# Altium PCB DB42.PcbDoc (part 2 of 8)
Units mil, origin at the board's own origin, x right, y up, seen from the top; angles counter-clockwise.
Board outline 3236.22 x 4456.69 mil, 8 copper layers (Top Layer, MidLayer1, MidLayer2, GND-Layer5, MidLayer3, VCC, MidLayer4, Bottom Layer), stack 62.194 mil thick; 214 components, 470 nets, 1802 pads, 1663 vias.
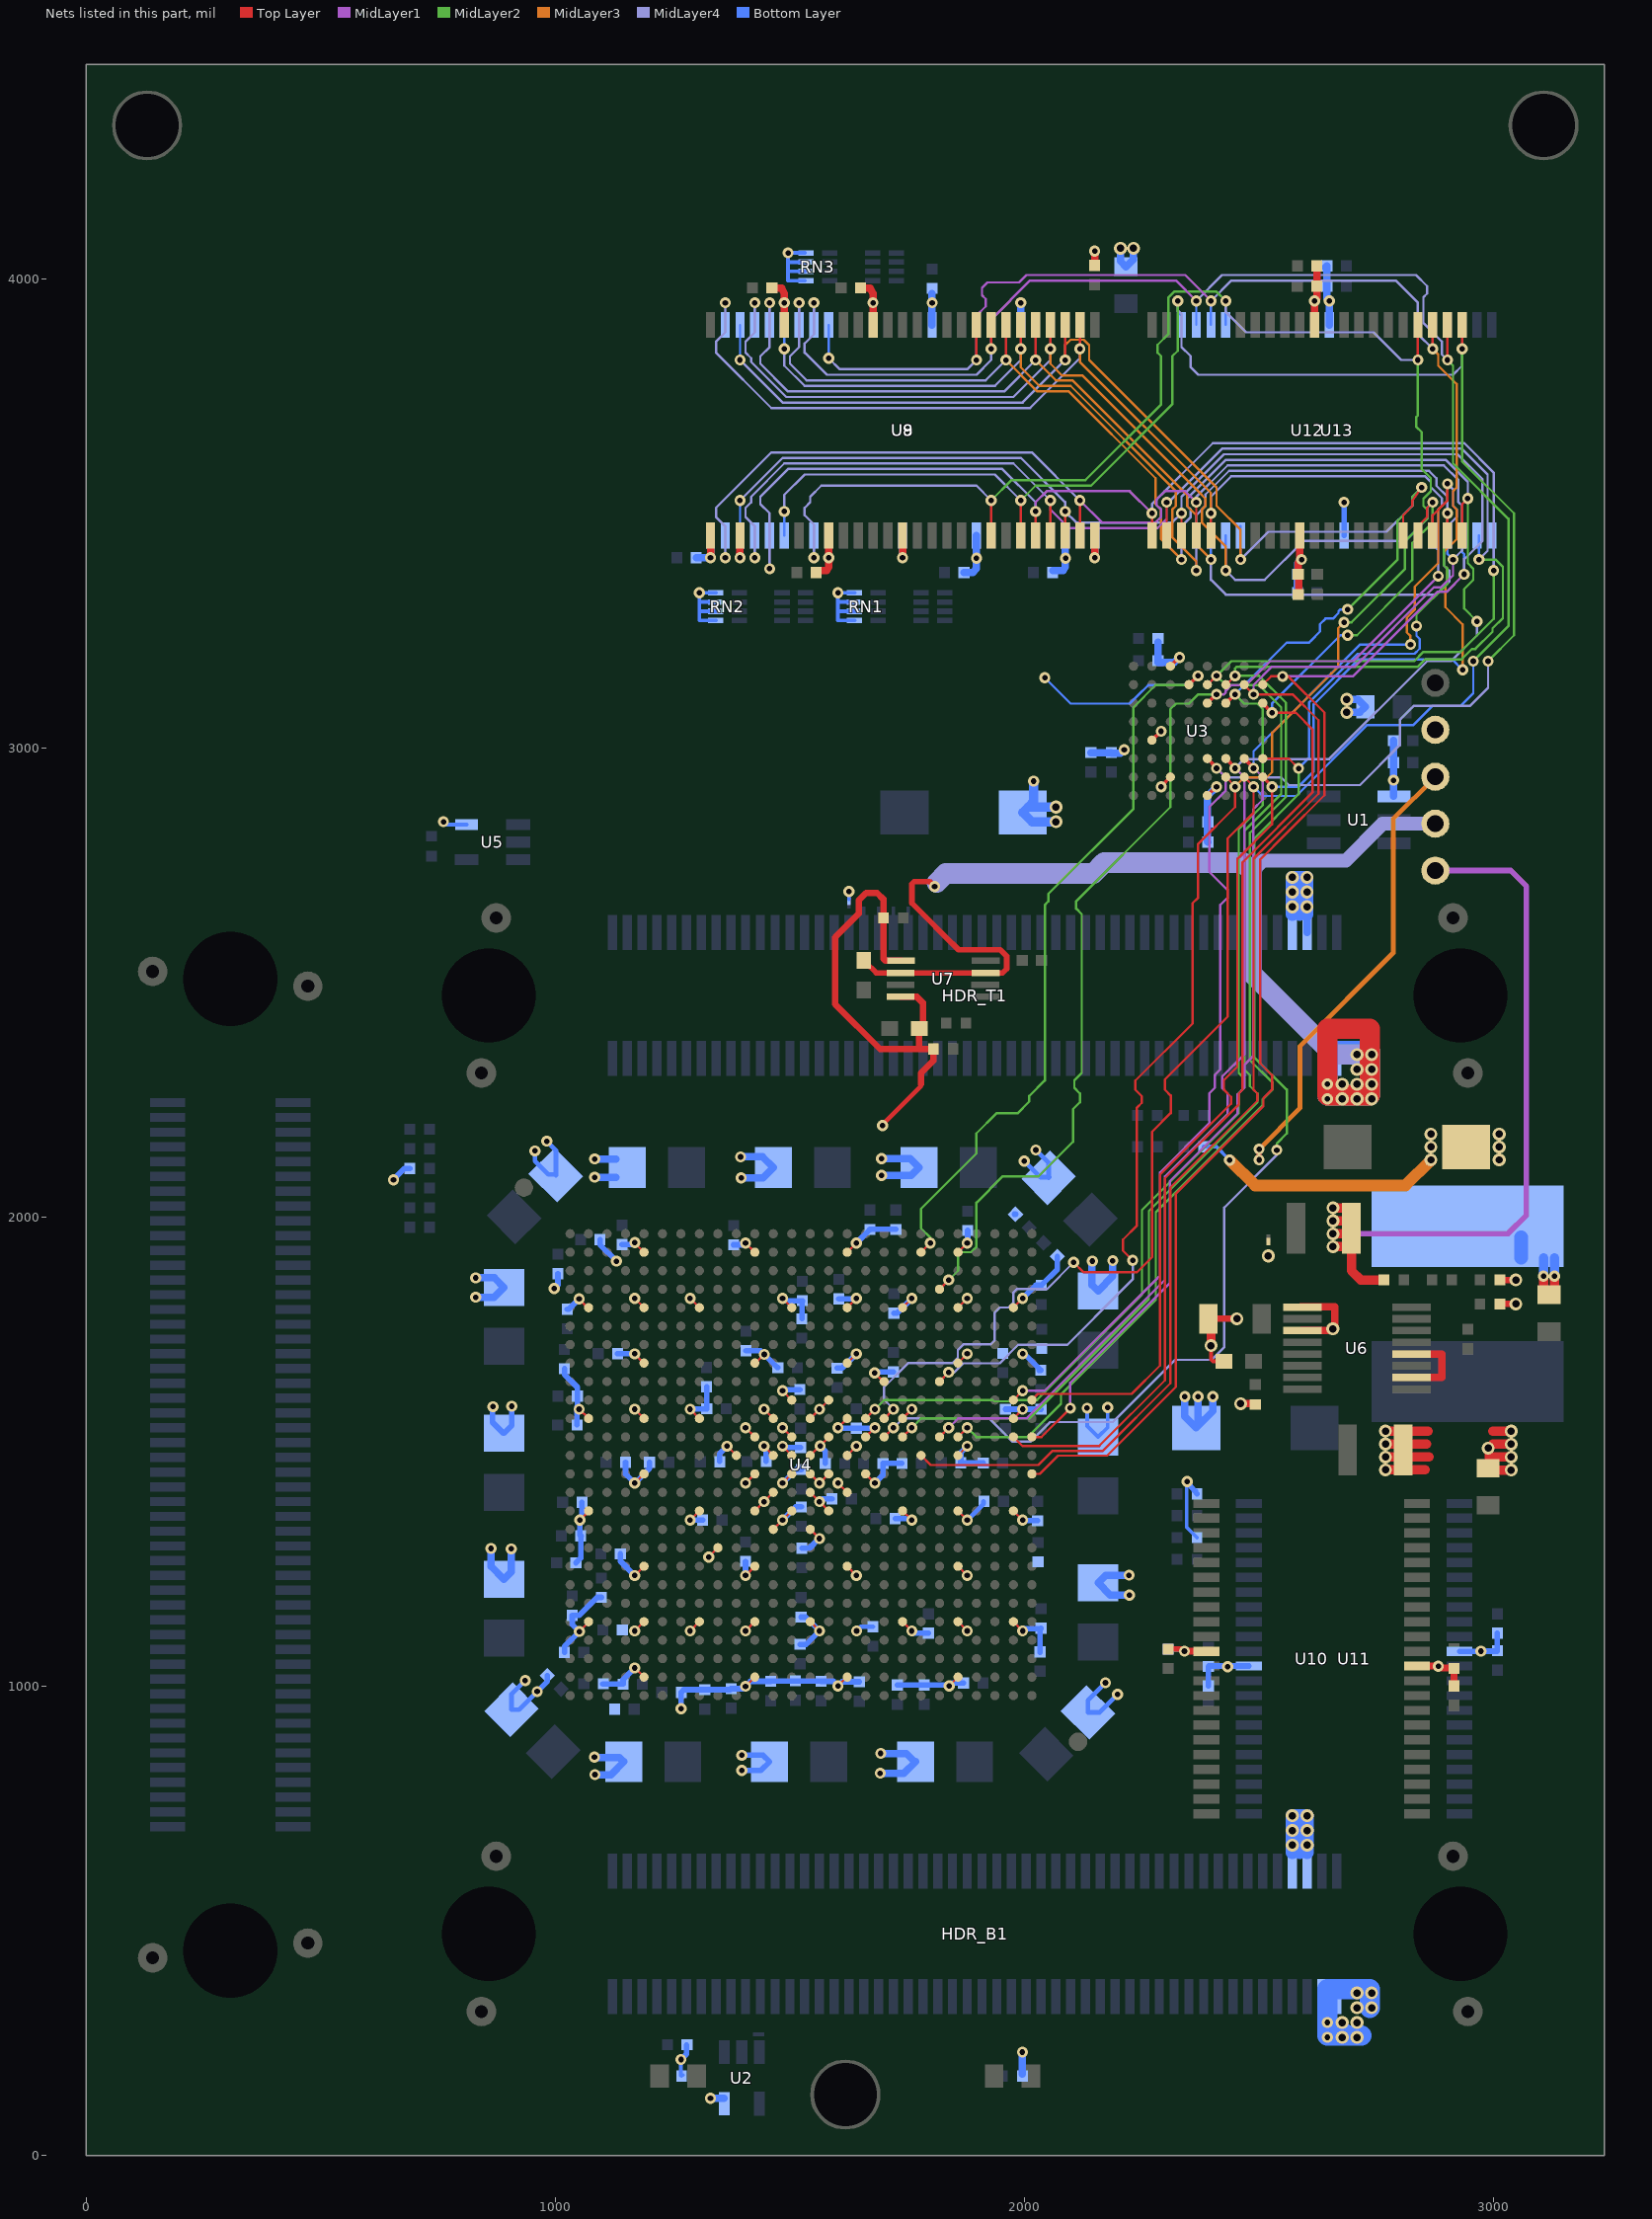
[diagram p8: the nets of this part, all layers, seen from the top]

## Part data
"Altium Logo Bot1" "Altium Logo Top1": library part D-000-0003, "Altium Logo for PCB"
C1 C11 C12 C13 C14 C23 C24 C25 C26 C27 C43 C44 C45 C46 C47 C48 C49 C50 C51 C52 C53 C54 C55 C56 C57 C58 C59 C60 C61 C62 C63 C64 C65 C66 C67 C68 C69 C101 C102 C103 C107 C121 C122 C123 C124 C129 C130 C133 C134 C137 C138 C139 C140: library part D-101-0080, "Capacitor, Ceramic, 0.1uF 10% 16V 0402 (1005) X7R"
C2 C15 C16 C17 C18 C28 C29 C30 C31 C32 C33 C34 C35 C36 C37 C38 C70 C71 C72 C73 C74 C75 C76 C77 C78 C79 C80 C81 C82 C83 C84 C85 C86 C87 C88 C89 C90 C91 C92 C93 C94 C95 C96 C97 C98 C104 C105 C106 C125 C126 C127 C128 C131 C132 C135 C136 C141 C142 C143 C144: library part D-101-0077, "Capacitor, Ceramic, 10nF 10% 16V 0402 (1005) X7R"
C3 C4 C5 C6 C7 C8 C9 C10 C19 C20 C21 C22 C39 C40 C41 C42: library part D-101-0007, "Capacitor, Tantalum, 10uF 10% 20V MCCT-B (3528)"
C99 C100 C112: library part D-101-0088, "Capacitor, Tantalum, 220uF 10% 10V MCCT-D (7343-31)"
C108 C109 C113 C115: library part D-101-0087, "Capacitor, Ceramic, 10uF 10% 10V 0805 (2012) X5R"
C110: library part D-101-0069, "Capacitor, Ceramic, 470pF 5% 50V 0402 (1005) COG"
C111 C118 C119: library part D-101-0095, "Capacitor, Ceramic, 2.2uF 10% 10V 0603 (1608) X5R"
C114 C116: library part D-101-0021, "Capacitor, Ceramic, 22uF -20%/+80% 10V 1210 (3225) Y5V"
C117: library part D-101-0027, "Capacitor, Ceramic, 1uF 10% 25V 1206 (3216) X7R"
C120: library part D-101-0105, "Capacitor, Ceramic, 0.033uF 10% 10V 0402 (1005) X7R"
HDR_B1 HDR_L1 HDR_T1: library part D-300-0025, "Connector, Molex Docking Station 100 Pin Male 54075"
L1: library part D-102-0004, "Inductor, 2.2uH, 15A, 4R2, SMD"
LED1: library part D-153-0004, "LED, Green 0805 (2012) KP-2012SGD"
LED2: library part D-153-0003, "LED, Red 0805 (2013) HSMH-C170"
MH1 MH2 MH3: library part D-001-0001, "Mounting Hole, M3 Screw, Plated, Square Pad"
NT1 NT2 NT3 NT4 NT5 NT6 NT7 NT8: library part D-002-0002, "Net-Tie, Surface Mount, 2 x 0.4mm x 0.2mm SMT Pads - For 0.2mm Track"
PCB1: library part D-810-0025, "DB42 Blank PCB - Daughter Board"
R1 R2 R9: library part D-100-0111, "Resistor, 270R 1% 0402 (1005)"
R3 R4 R5 R6 R7 R8 R14 R15 R16 R17: library part D-100-0131, "Resistor, 100R 1% 0402 (1005)"
R10 R11 R12 R13: library part D-100-0088, "Resistor, 4K7 1% 0402 (1005)"
R18 R23 R24 R25: library part D-100-0132, "Resistor, 100K 1% 0402 (1005)"
R19: library part D-100-0128, "Resistor, 10R 1% 0402 (1005)"
R20 R22: library part D-100-0105, "Resistor, 2K7 1% 0402 (1005)"
R21: library part D-100-0109, "Resistor, 27K 1% 0402 (1005)"
RN1 RN2 RN3 RN4 RN5 RN6: library part D-104-0001, "Resistor Network, Isolated, 4 x 100R, 5%, SMD 0402 x 4"
TP1 TP2 TP3 TP4 TP5: library part D-006-0000, "Test Point, PCB Mount with Silkscreen Box"
U1: library part D-263-0002, "Dual Addressable Switch Plus 1KB Memory"
U2 U5: library part D-205-0001, "SN74LVC1G04DBV, Single Inverter Gate, 1.65-V to 5.5-V"
U3: library part D-262-0001, "S29GL256N11FFIV10, 256 Megabit (16M x 16) 3.0V Page Mode Flash Memory"
U4: library part D-241-0013, "FPGA, Xilinx Spartan 3A-DSP-1800 FG676"
U6: library part D-204-0002, "MAX1831EEE, 3A, 1MHz, Low-Voltage, Step-Down Regulators with Synchronous Rectification and Internal Switches"
U7: library part D-204-0016, "MAX8860EUA18+, 1.8V Linear Regulator with adjustable Output, Low-noise, Low-dropout, 300mA, uMAX"
U8 U9: library part D-261-0000, "MT48LC16M16A2TG, 256 Mbit High-Speed CMOS SDRAM, 16Mb x 16Bit x 4 Banks, TSOP54"
U10 U11 U12 U13: library part D-260-0000, "K6R4016V1D-TC10T, 256K x 16-Bit SRAM, TSOP44"

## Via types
v1: diameter 23.62, hole 11.81, Top Layer to Bottom Layer, 1081 vias
v2: diameter 23.62, hole 11.81, Top Layer to Bottom Layer, tented both sides, 466 vias
v3: diameter 27.56, hole 15.75, Top Layer to Bottom Layer, 116 vias

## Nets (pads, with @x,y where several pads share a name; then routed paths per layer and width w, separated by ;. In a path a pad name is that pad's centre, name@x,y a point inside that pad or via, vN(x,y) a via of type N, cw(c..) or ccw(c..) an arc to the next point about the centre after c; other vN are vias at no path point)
1V2: C3.1 C4.1 C5.1 C6.1 C7.1 C8.1 C9.1 C10.1 C11.1 C12.1 C13.1 C14.1 C15.1 C16.1 C17.1 C18.1 C112.1 C115.1 C116.1 L1.2 R20.1 TP5.1 U4.K15 U4.L12 U4.L14 U4.L16 U4.M11 U4.M13 U4.M15 U4.M17 U4.N12 U4.N13 U4.N14 U4.N16 U4.P11 U4.P13 U4.P14 U4.P15 U4.R12 U4.R14 U4.R16 U4.T11 U4.T13 U4.T15 U4.U12 | length 4291.5
  Top Layer w5: v1(1405.51,1433.07) U4.P11@1425.2,1452.76 ; v1(1405.51,1551.18) U4.M11@1425.2,1531.5 ; U4.T11@1425.2,1374.02 v1(1444.88,1393.7) U4.R12@1464.57,1413.39 ; v1(1444.88,1511.81) U4.N12@1464.57,1492.13 ; v1(1444.88,1590.55) U4.L12@1463.37,1572.06 ; U4.U12@1464.57,1334.65 v1(1484.25,1354.33) U4.T13@1503.94,1374.02 ; U4.L12@1464.57,1570.87 U4.L12@1463.37,1572.06 ; U4.L12@1465.29,1572.06 1464.57,1572.06 U4.L12@1463.37,1572.06 ; v1(1484.25,1433.07) U4.P13@1503.94,1452.76 ; v1(1484.25,1511.81) U4.N13@1503.94,1492.13 ; v1(1484.25,1551.18) U4.M13@1503.94,1531.5 ; U4.L14@1542.52,1570.47 1542.91,1570.47 U4.L14@1543.31,1570.87 v1(1562.99,1590.55) ; U4.R14@1543.31,1413.39 v1(1562.99,1393.7) U4.T15@1582.68,1374.02 ; U4.P14@1543.31,1452.76 v1(1562.99,1433.07) U4.P15@1582.68,1452.76 ; U4.N14@1543.31,1492.13 v1@1562.99,1511.81 ; v1@1562.99,1590.95 v1(1562.99,1590.55) ; v1@1564,1589.55 v1@1564.57,1590.12 ; v1(1564.57,1512.21) 1582.68,1530.31 U4.M15@1582.68,1531.5 U4.M15@1583.46,1531.5 ; U4.K15@1582.68,1610.24 v1(1562.99,1590.55) ; v1(1602.36,1433.07) U4.R16@1622.05,1413.39 ; v1(1602.36,1551.18) U4.L16@1622.05,1570.87 ; v1@1602.76,1550.79 v1@1603.54,1551.57 ; U4.N16@1622.05,1492.13 v1(1641.73,1511.81) ; U4.M17@1661.42,1531.5 v1(1681.1,1551.18)
  Top Layer w19.68: C116.1@2694.88,1974.4 2692.91,1976.37 2694.88,1978.34 C116.1@2704.72,1988.19 ; C116.1@2696.85,1976.37 2696.85,1948.82 2696.85,1885.83 2716.54,1866.14 R20.1@2766.22,1866.14 ; C115.1@3106.3,1834.64 v1(3106.3,1874.02) ; C115.1@3129.92,1834.64 v1(3129.92,1874.02)
  Top Layer w20: v3(2657.47,1937) C116.1@2696.85,1937 ; v3(2657.47,1964.56) C116.1@2696.85,1964.56 ; v3(2657.47,1992.12) C116.1@2696.85,1992.12 ; v3(2657.47,2019.68) C116.1@2696.85,2019.68
  MidLayer1 w12: v3(2657.47,1964.56) 3030.56,1964.56 3070,2004 3070,2705 3036.33,2738.67 TP5.1@2875.71,2738.67
  Bottom Layer w11.81: C14.1@1095.2,1952.26 1095.2,1941.36 v1(1130.39,1906.17) ; v1@1444.88,1512.99 1445.47,1512.4 1448.82,1509.06 C17.1@1448.82,1479.92 ; v1(1484.25,1354.33) 1512.45,1382.53 C16.1@1524.22,1382.53 ; v1(1484.25,1433.07) 1513.41,1462.23 C13.1@1524.22,1462.23 ; v1(1562.99,1393.7) 1568.9,1399.61 C12.1@1589.57,1399.61 ; v1(1564.57,1512.21) 1575.38,1501.4 C11.1@1575.38,1475.02 ; v1@1603.15,1551.97 1604.92,1550.2 C18.1@1641.73,1550.2 1680.12,1550.2 v1(1681.1,1551.18)
  Bottom Layer w12: v1(1484.25,1511.81) 1487.2,1508.86 C15.1@1522.64,1508.86
  Bottom Layer w15.75: v2(830.5,1829.26) 869.34,1829.26 C10.1@890.44,1850.36 870.22,1870.58 v2(830.5,1870.58) ; v1(862.97,1293.96) 862.97,1255.91 C8.1@890.44,1228.43 906.26,1244.26 v1(906.26,1292.98) ; v1@1082.4,848.21 1083.38,848.21 1136.82,848.21 C9.1@1145.76,839.26 1118.3,811.8 v1(1084.37,811.8) ; v2(1083.89,2123.88) C6.1@1128.89,2123.88 ; v2(1083.94,2084.97) C6.1@1128.94,2084.97 ; v1(1693.46,857.06) 1747.79,857.06 C7.1@1766.64,838.21 ; v1@1694.36,814.34 1742.76,814.34 C7.1@1767.69,839.26 ; v2(1695.43,2089.03) 1758.89,2089.03 C5.1@1775.57,2105.71 1756.82,2124.46 v2(1695.43,2124.46) ; v1@2144.14,1906.99 2144.14,1906.3 2144.14,1855.25 C3.1@2156.88,1842.5 2188.19,1873.81 v1(2188.19,1907.09) ; v1(2222.86,1236.89) 2173.23,1236.89 C4.1@2156.9,1220.56 2182.88,1194.58 v1(2223.84,1194.58) v1@2224.82,1194.58 ; v1(2341.79,1617.56) 2341.79,1575.19 C112.1@2366.07,1550.91 C112.1@2370.08,1554.92 ; v1(2370.08,1617.56) C112.1@2370.08,1554.92 ; v1(2401.58,1617.56) 2401.58,1586.42 C112.1@2370.08,1554.92
  Bottom Layer w19.68: v1(3106.3,1874.02) L1.2@3106.3,1913.39 ; v1(3129.92,1874.02) L1.2@3129.92,1913.39
  Bottom Layer w29.53: L1.2@3059.06,1913.38 L1.2@3059.06,1956.69
  other v1: 1692.48,814.75 1083.38,849.19 2144.88,1906.3
2V5: C19.1 C20.1 C21.1 C22.1 C23.1 C24.1 C25.1 C26.1 C27.1 C28.1 C29.1 C30.1 C31.1 C32.1 C33.1 C34.1 C35.1 C36.1 C37.1 C38.1 C118.1 R18.2 R24.1 TP3.1 U4.AB5 U4.AB11 U4.AB22 U4.E5 U4.E16 U4.E22 U4.J18 U4.K13 U4.L5 U4.N10 U4.P17 U4.T22 U4.U14 U4.V9 U7.1 U7.4 | length 3482.1
  Top Layer w5: v1(1169.29,1118.11) U4.AB5@1188.98,1137.8 ; v1(1169.29,1590.55) U4.L5@1188.98,1570.87 ; v1(1169.29,1826.77) U4.E5@1188.98,1807.09 ; v1(1326.77,1275.59) U4.V9@1346.46,1295.28 ; v1(1366.14,1511.81) U4.N10@1385.83,1492.13 ; v1(1405.51,1118.11) U4.AB11@1425.2,1137.8 ; v1(1484.25,1629.92) U4.K13@1503.94,1610.24 ; U4.U14@1543.31,1334.65 v1(1562.99,1314.96) ; U4.E16@1622.05,1807.09 v1(1641.73,1826.77) ; U4.P17@1661.42,1452.76 v1(1681.1,1433.07) ; v1(1680.71,1668.11) 1699.21,1649.61 U4.J18@1700.79,1649.61 ; 1779.53,2279.53 1779.53,2283.46 ; U4.AB22@1858.27,1137.8 v1(1877.95,1118.11) ; U4.T22@1858.27,1374.02 v1(1877.95,1354.33) ; U4.E22@1858.27,1807.09 v1(1877.95,1826.77)
  Top Layer w10: v1(1697.4,2195.3) 1697.4,2197.27 1771.2,2271.07 ; 1759.84,2259.84 1779.53,2279.53
  Top Layer w13.78: U7.4@1736.22,2469.48 1770.67,2469.48 1783.46,2456.69 1783.46,2413.39 C118.1@1775.59,2405.51 ; U7.1@1737.2,2546.26 1703.75,2546.25 1699.29,2550.71 R24.1@1699.29,2637.79 1699.29,2677.68 1686.02,2690.94 1662.4,2690.94 1646.65,2675.2 1646.65,2646.65 1596.46,2596.46 1596.46,2453.74 1691.93,2358.26 R18.2@1805.59,2358.26 ; 1775.59,2358.27 C118.1@1775.59,2401.57 ; 1779.53,2283.46 1779.53,2307.09 1795.28,2322.83 1805.59,2333.15 R18.2@1805.59,2354.33
  MidLayer3 w10: v1(2500,2122.05) v1(2500,2145) 2587,2232 2587,2364 2786,2563 2786,2848.96 TP3.1@2875.71,2938.67
  Bottom Layer w10: v1(935.78,1012.54) 906.46,983.21 C20.1@906.46,950.02 922.47,950.02 v1(961.37,988.92) ; v1(956.45,2141.18) 956.45,2119.54 984.98,2091 C22.1@1001.11,2091 ; v1(982.03,2161.85) 1001.11,2142.77 C22.1@1001.11,2091 ; C22.1@1001.11,2089.53 C22.1@1001.11,2091 ; v1(1642.06,1117.99) 1651.04,1126.97 C33.1@1677.17,1126.97 ; v1(1877.95,1354.33) 1912.87,1389.25 C28.1@1912.87,1393.97 ; v1(1999.49,2119.54) 2033.93,2085.1 C21.1@2051.71,2085.1 ; v1(2024.09,2143.15) 2051.71,2115.53 C21.1@2051.71,2085.1 ; C21.1@2051.71,2083.96 C21.1@2051.71,2085.1 ; C21.1@2052.62,2085.1 C21.1@2051.71,2085.1 ; v1(2172.67,1007.62) 2135.22,970.17 C19.1@2135.22,944.46 2159.7,944.46 v1(2198.26,983.02)
  Bottom Layer w11.81: v1(961.37,988.92) 983.16,1010.71 C35.1@983.16,1023.22 ; v1(1484.25,1629.92) 1486.79,1632.46 C37.1@1521.26,1632.46 ; v1(1681.1,1433.07) 1698.39,1450.36 C29.1@1698.39,1475.02 C23.1@1738.72,1475.02 ; C31.1@1978.67,2006.23 C31.1@1980.94,2006.23
  Bottom Layer w12: C30.1@1350,1479.53 1350,1495.67 v1(1366.14,1511.81) ; C27.1@1525.59,1294.29 1541.54,1294.29 v1@1561.81,1314.57 ; C26.1@1604.33,1825.79 1640.75,1825.79 v1(1641.73,1826.77) ; v1(1680.71,1668.11) 1682.87,1670.28 C24.1@1720.47,1670.28
3V3: C1.2 C2.1 C39.1 C40.1 C41.1 C42.1 C43.1 C44.1 C45.1 C46.1 C47.1 C48.1 C49.1 C50.1 C51.1 C52.1 C53.1 C54.1 C55.1 C56.1 C57.1 C58.1 C59.1 C60.1 C61.1 C62.1 C63.1 C64.1 C65.1 C66.1 C67.1 C68.1 C69.1 C70.1 C71.1 C72.1 C73.1 C74.1 C75.1 C76.1 C77.1 C78.1 C79.1 C80.1 C81.1 C82.1 C83.1 C84.1 C85.1 C86.1 C87.1 C88.1 C89.1 C90.1 C91.1 C92.1 C93.1 C94.1 C95.1 C96.1 C97.1 C98.1 C99.1 C100.1 C101.2 C102.1 C103.1 C104.1 C105.1 C106.1 C107.1 C108.1 C109.1 C121.1 C122.1 C123.1 C124.1 C125.1 C126.1 C127.1 C128.1 C129.1 C130.1 C131.1 C132.1 C133.1 C134.1 C135.1 C136.1 C137.1 C138.1 C139.1 C140.1 C141.1 C142.1 C143.1 C144.1 HDR_B1.94 HDR_B1.96 HDR_T1.94 HDR_T1.96 NT1.2 R1.1 R2.1 R10.2 R11.2 R12.2 R13.2 RN1.1 RN1.2 RN1.3 RN1.4 RN2.1 RN2.2 RN2.3 RN2.4 RN3.1 RN3.2 RN3.3 RN3.4 TP2.1 U1.4 U2.5 U3.D8 U3.F1 U3.F7 U3.G5 U4.AB2 U4.AB8 U4.AB14 U4.AB19 U4.AB25 U4.AE5 U4.AE11 U4.AE16 U4.AE22 U4.B5 U4.B11 U4.B16 U4.B22 U4.E2 U4.E8 U4.E13 U4.E19 U4.E25 U4.H5 U4.H11 U4.H16 U4.H22 U4.L2 U4.L8 U4.L19 U4.L25 U4.N22 U4.P5 U4.T2 U4.T8 U4.T19 U4.T25 U4.W5 U4.W11 U4.W16 U4.W22 U5.5 U8.1 U8.3 U8.9 U8.14 U8.27 U8.43 U8.49 U9.1 U9.3 U9.9 U9.14 U9.27 U9.43 U9.49 U10.11 U10.33 U11.11 U11.33 U12.11 U12.33 U13.11 U13.33 | length 9406.7
  Top Layer w5: v1@1046.97,1591.42 v1(1050.79,1590.55) 1070.87,1571.42 U4.L2@1070.87,1570.87 ; v1(1050.8,1825.8) 1050.08,1825.98 1050.53,1825.53 1069.92,1806.14 1070.04,1806.02 U4.E2@1070.31,1806.02 ; v1(1051.38,1116.81) 1051.38,1117.09 1070.87,1136.57 U4.AB2@1070.87,1137.8 ; v2(1052.37,1354.18) U4.T2@1070.83,1372.64 ; U4.T2@1068.46,1373.94 U4.T2@1070.04,1373.94 ; U4.T2@1069.25,1372.64 U4.T2@1070.83,1372.64 ; U4.T2@1070.87,1372.67 U4.T2@1070.87,1374.02 ; U4.T2@1071.57,1372.64 U4.T2@1070.87,1372.64 ; v1(1169.29,1236.22) U4.W5@1188.98,1255.91 ; v1(1169.29,1433.07) U4.P5@1188.98,1452.76 ; v1@1169.29,1944.88 U4.B5@1188.98,1925.2 ; v1@1169.68,1707.87 1187.8,1689.76 1188.98,1689.76 U4.H5@1190.16,1689.76 ; v1@1169.98,1039.1 1188.98,1020.1 U4.AE5@1188.98,1019.68 ; v1(1287.4,1118.11) U4.AB8@1307.09,1137.8 ; v1(1287.4,1354.33) U4.T8@1307.09,1374.02 ; v1(1287.4,1590.55) U4.L8@1307.09,1570.87 ; v1(1287.4,1826.77) U4.E8@1307.09,1807.09 ; v1(1405.51,1000) U4.AE11@1425.2,1019.68 ; v1(1405.51,1236.22) U4.W11@1425.2,1255.91 ; v1(1405.51,1944.88) U4.B11@1425.2,1925.2 ; U4.H11@1425.2,1688.98 1426.77,1688.98 v1(1445.28,1707.48) ; v1(1484.25,1826.77) U4.E13@1503.94,1807.09 ; U4.AB14@1543.31,1137.8 v1(1562.99,1118.11) ; U8.9@1582.68,3433.07 U8.9@1582.68,3452.76 ; v1(1602.4,1000.98) 1621.1,1019.68 U4.AE16@1622.05,1019.68 ; U4.W16@1622.05,1255.91 v1(1641.73,1236.22) ; U4.H16@1622.05,1688.98 v1(1641.73,1708.66) ; U4.B16@1622.05,1925.2 v1(1641.73,1944.88) ; U4.AB19@1740.16,1137.8 v1(1759.84,1118.11) ; U4.T19@1740.16,1374.02 v1(1759.84,1354.33) ; U4.L19@1740.16,1570.87 v1(1759.84,1590.55) ; U4.E19@1740.16,1807.09 v1(1759.84,1826.77) ; v1(1839.33,1000.71) U4.AE22@1858.27,1019.65 ; U4.W22@1858.27,1255.91 v1(1877.95,1236.22) ; U4.N22@1858.27,1492.13 v1(1877.95,1511.81) ; U4.H22@1858.27,1688.98 v1(1877.95,1708.66) ; U4.B22@1858.27,1925.2 v1(1877.95,1944.88) ; U4.AB25@1976.38,1137.8 v1(1996.06,1118.11) ; U4.T25@1976.38,1374.02 v1(1996.06,1354.33) ; U4.L25@1976.38,1570.87 v1(1996.06,1590.55) ; U4.E25@1976.38,1807.09 v1(1996.06,1826.77)
  Top Layer w7.87: U3.G5@2271.65,3016.73 v1(2291.34,3035.43) ; v1@2291.34,2918.31 U3.F7@2311.02,2937.99 ; U3.F1@2311.02,3174.21 2330.22,3193.41 v1@2330.71,3193.9 ; U3.D8@2389.76,2898.62 2408.96,2917.82 v1@2409.45,2918.31
  Top Layer w12: C130.1@2306.5,1079.45 2336.55,1079.45 v1(2341,1075)
  Top Layer w15: v1@2343,1075 2343.2,1074.8 U10.33@2387.89,1074.8 ; U10.11@2836.71,1043.3 v1@2881.7,1043.3 ; v1(2882,1043) v1@2881.7,1043.3 ; C131.1@2915.44,1000.98 C129.1@2915.44,1038.37 2914.45,1039.37 2889.76,1039.37 2885.83,1043.3 2882,1043.3 v1@2881.7,1043.3
  Top Layer w15.75: v2@1330.71,3409.45 U8.1@1330.71,3452.76 ; v2(1393.7,3405.51) U8.3@1393.7,3452.76 ; C125.1@1461.61,3980.31 1482.28,3980.32 1488.19,3968.51 ; U8.49@1488.19,3901.57 v2(1488.19,3948.82) ; v2@1488.19,3944.88 v2(1488.19,3948.82) ; 1488.19,3964.57 v2(1488.19,3948.82) ; C122.1@1556.1,3377.95 1578.74,3377.95 1582.68,3385.83 1582.68,3389.76 1583.46,3401.52 1583.58,3403.35 v2@1583.66,3404.53 ; U8.9@1582.68,3452.76 v2@1582.68,3409.45 ; C126.1@1650.59,3980.31 1671.26,3980.32 1677.17,3968.51 v2(1677.17,3948.82) ; U8.43@1677.17,3901.57 v2(1677.17,3948.82) ; v2@1677.17,3944.88 v2(1677.17,3948.82) ; v2(1740.16,3405.51) U8.14@1740.16,3452.76 ; v2(2149.6,3405.52) U8.27@2149.61,3452.76 ; C121.1@2149.6,4028.54 v2(2149.61,4059.06) ; C141.1@2582.4,3371.05 C141.1@2583.38,3370.07 2583.38,3394.4 v2(2590.55,3401.57) 2586.61,3405.51 U12.11@2586.61,3452.76 ; C137.1@2584.37,3329.71 2584.37,3370.07 C141.1@2584.34,3370.23 ; U12.33@2618.11,3901.57 v2(2618.11,3952.76) 2623.03,3957.67 2623.03,3984.24 C138.1@2623.03,4027.55 ; v2@1582.68,3409.45 v2@1583.43,3405.66 ; v2@1582.68,3409.45 v2@1583.43,3405.66 ; v2@1583.43,3405.66 v2@1583.66,3404.53 ; v2@1583.43,3405.66 v2@1583.66,3404.53
  MidLayer3 w25: v1(2437.37,2121.5) 2491.49,2067.38 2812.27,2067.38 2866.14,2121.25 v3(2866.14,2122.05)
  Bottom Layer w5: v1@1046.26,1586.81 v1(1050.79,1590.55) ; v1@1049.41,1117.13 1050.55,1115.98 v1@1050.79,1115.75 ; v1(1268.07,952.24) v1@1268.31,952.48
  Bottom Layer w7.87: v1(1267.72,204.72) 1267.72,170.78 R1.1@1269.21,169.29 R1.1@1271.65,171.73 ; C101.2@1279.53,235.24 C101.2@1280.51,236.22 ; RN2.1@1342.51,3271.65 RN2.1@1341.54,3271.65 1307.09,3271.65 1307.09,3291.34 ; RN2.2@1342.51,3291.34 RN2.2@1341.54,3291.34 1307.09,3291.34 ; RN2.3@1342.51,3311.02 RN2.3@1341.54,3311.02 1307.09,3311.02 ; RN2.4@1342.51,3330.71 RN2.4@1341.54,3330.71 v1(1307.09,3330.71) 1307.09,3311.02 ; U2.5@1359.25,122.05 U2.5@1360.23,123.03 ; RN3.1@1531.49,3996.06 1496.07,3996.06 1496.07,4015.74 ; RN3.2@1531.49,4015.74 1496.07,4015.74 ; RN3.3@1531.49,4035.43 1496.07,4035.43 ; RN3.4@1531.49,4055.11 v1(1496.07,4055.11) 1496.07,4035.43 ; NT1.2@1625.98,2677.17 v2@1625.98,2688.98 ; RN1.1@1637.79,3271.65 1602.36,3271.65 1602.36,3291.34 ; RN1.2@1637.79,3291.34 1602.36,3291.34 ; RN1.3@1637.79,3311.02 1602.36,3311.02 ; RN1.4@1637.79,3330.71 v1(1602.36,3330.71) 1602.36,3311.02 ; 1307.09,3291.34 1307.09,3311.02 ; 1496.07,4015.74 1496.07,4035.43 ; 1602.36,3291.34 1602.36,3311.02
  Bottom Layer w8: v1(761.62,2842.78) 767.51,2836.88 U5.5@810.8,2836.88 ; v1(2133.46,1592.91) 2133.46,1554.98 C40.1@2156.9,1531.55 2177.17,1551.81 v1(2177.17,1594.49) ; 2345.8,1393.34 2345.8,1435.6 v1(2346.84,1436.64) ; 2345.8,1416.96 2345.8,1434.62 v1@2345.86,1434.67 ; v1@2346.5,1435.8 v1@2347.27,1434.87 ; v1@2347.35,1434.95 v1@2347.27,1434.87 ; R13.2@2366.65,1411.41 R13.2@2366.65,1416.83 ; R12.2@2367.64,1317.04 2345.8,1338.88 2345.8,1433.4 v1@2347.27,1434.87 ; R11.2@2381.92,2150.17 2408.71,2150.17 v1(2437.37,2121.5)
  Bottom Layer w11: v1@2347.27,1434.87 R13.2@2367.64,1410.21
  Bottom Layer w11.81: v1@655.51,2080.71 678.53,2103.73 R10.2@689.74,2103.73 ; C62.1@1046.26,1557.09 v1@1046.26,1586.81 ; v1@1046.26,1595.08 1046.98,1594.36 v1(1050.79,1590.55) ; C44.1@1149.61,1477.36 1149.61,1452.75 v1(1169.29,1433.07) 1200.79,1464.57 C46.1@1200.79,1477.36 ; v1(1267.72,204.72) 1279.53,216.54 C101.2@1279.53,235.24 ; v1@1268.31,952.48 C66.1@1268.31,987.2 ; v1(1287.4,1354.33) C71.1@1313.98,1354.33 ; v1(1287.4,1590.55) 1288.38,1591.54 C77.1@1322.83,1591.54 ; C97.1@1379.92,1940.94 1401.57,1940.95 v1(1405.51,1944.88) ; v1(1405.51,1236.22) C49.1@1405.51,1266.34 ; C78.1@1406.5,1715.55 1437.2,1715.55 v1(1445.28,1707.48) 1473.62,1679.13 C45.1@1474.41,1679.13 ; v1(1484.25,1826.77) 1489.17,1821.85 C79.1@1526.57,1821.85 ; C52.1@1521.65,1089.57 1534.45,1089.57 v1(1562.99,1118.11) 1533.46,1147.64 C53.1@1523.62,1147.64 ; C51.1@1525.59,1783.46 1525.59,1819.29 C79.1@1526.38,1820.08 ; v1@1598.66,997.24 v1(1602.4,1000.98) ; C70.1@1600.39,1678.15 1611.22,1678.15 v1(1641.73,1708.66) ; C56.1@1721.46,1795.28 1728.35,1795.28 v1(1759.84,1826.77) ; C76.1@1724.41,1357.28 1756.89,1357.28 v1(1759.84,1354.33) ; v1(1759.84,1118.11) 1764.76,1113.19 C54.1@1795.28,1113.19 ; C86.1@1786.42,1002.95 1837.09,1002.95 v1(1839.33,1000.71) 1845.51,1006.89 C55.1@1870.08,1006.89 ; C50.1@1864.17,1476.38 1864.17,1498.03 v1(1877.95,1511.81) v1@1881.89,1515.75 ; v1(1877.95,1944.88) 1878.94,1945.87 C64.1@1878.94,1971.46 ; C75.1@1959.65,1590.55 v1(1996.06,1590.55) ; v1(1996.06,1118.11) 2000.99,1123.03 C89.1@2034.45,1123.03 ; v1(1996.06,1826.77) v1@1997.05,1827.76 ; v1@1997.24,1590.55 C67.1@2035.43,1590.55 ; C93.1@2032.94,1072.56 C93.1@2032.94,1073.55 2032.94,1121.53 C89.1@2034.45,1123.03 ; C89.1@2035.43,1123.03 C89.1@2034.45,1123.03 ; C89.1@2035.43,1124.02 C89.1@2034.45,1123.03 ; C133.1@2391.82,1000.98 C135.1@2391.82,1042.31 2392.81,1043.3 2433,1043.3 v1@2434.3,1043.3 ; v1(2433,1042) v1@2434.3,1043.3 ; U11.11@2478.44,1043.3 v1@2434.3,1043.3 ; U13.11@2681.1,3452.76 v2(2681.1,3523.62) ; U11.33@2927.25,1074.79 2972.79,1074.79 v1(2973,1075) 3007.08,1075 C136.1@3007.87,1075.78 C134.1@3007.87,1113.18
  Bottom Layer w12: v1@865.92,1596.05 865.92,1562.59 889.09,1539.42 C42.1@890.44,1539.42 890.97,1539.42 907.25,1555.7 v1(907.25,1597.03) ; v1(997.48,1847.72) 1005.65,1855.88 C65.1@1005.65,1879.43 ; C83.1@1019.42,1072.56 1019.42,1084.85 1050.55,1115.98 v1(1051.38,1116.81) 1036.15,1132.04 C60.1@1036.15,1151.27 1050.91,1151.28 1089.28,1189.65 C73.1@1098.14,1189.65 ; C68.1@1019.42,1676.73 1019.42,1664.93 1046.98,1637.37 C72.1@1046.98,1618.68 1046.98,1594.36 v1(1050.79,1590.55) ; C85.1@1025.33,1803.68 1028.68,1803.68 v1(1050.8,1825.8) ; C98.1@1044.03,1263.46 1054.13,1273.56 C57.1@1054.13,1320.87 ; C57.1@1054.85,1320.15 C57.1@1054.13,1320.87 ; C69.1@1056.82,1392.36 1056.82,1358.63 v2(1052.37,1354.18) 1052.37,1322.63 C57.1@1054.13,1320.87 ; C92.1@1101.1,1004.66 1102.09,1004.66 C84.1@1144.39,1004.66 1144.39,1014.5 v1(1168.99,1039.1) ; C94.1@1132.59,1709.21 1168.57,1709.21 1169.2,1708.57 v1@1171.36,1706.41 ; C59.1@1138.49,1282.15 1138.49,1267.02 v1(1169.29,1236.22) ; C63.1@1142.42,1941.43 1164.85,1941.43 v1(1169.39,1945.97) ; C66.1@1268.31,987.2 1273.96,992.86 C91.1@1318.56,992.86 1372.68,992.86 C90.1@1374.65,994.83 1400.34,994.83 v1(1405.51,1000) 1416.09,1010.57 C47.1@1459.27,1010.57 1460.26,1011.56 C82.1@1511.42,1011.56 1565.54,1011.56 C61.1@1566.53,1010.57 1592.81,1010.57 v1(1602.4,1000.98) 1611.01,1009.59 C80.1@1648.2,1009.59 ; C77.1@1322.5,1593.1 C48.1@1322.5,1638.35 ; v1(1397.28,820.66) 1438.13,820.66 C39.1@1456.74,839.26 1442.88,853.13 v1(1397.28,853.13) ; v1(1641.73,1944.88) 1670.75,1973.9 C96.1@1670.83,1973.9 ; C96.1@1671.31,1973.43 C96.1@1670.83,1973.9 ; C81.1@1725.94,1973.9 C96.1@1670.83,1973.9 ; C95.1@1728.89,1002.7 1786.17,1002.7 C86.1@1786.42,1002.95 ; C50.1@1864.17,1476.38 1864.55,1476 C43.1@1911.91,1476 ; v1(1996.06,1354.33) 1997.4,1352.99 C88.1@2028.02,1352.99 ; v1(1996.06,1708.66) 2000.04,1708.66 C58.1@2034.91,1673.79 C58.1@2030.94,1673.79 ; v1(1996.06,1826.77) 2024.14,1854.85 C87.1@2035.9,1854.85 2070.19,1889.14 C74.1@2070.19,1915.99 ; C132.1@2306.5,1079.45 2336.55,1079.45 v1(2341,1075)
  Bottom Layer w15.75: C123.1@1300.19,3405.5 v2(1330.71,3405.51) ; U9.27@1329.73,3437.99 U9.27@1330.71,3437.01 ; v1(1330.71,122.05) U2.5@1359.25,122.05 ; v2@1330.71,3404.53 v2(1330.71,3405.51) ; U9.27@1330.71,3452.76 U9.27@1330.71,3437.01 ; v1@1394.91,2083.43 v1(1396.06,2083.46) 1442.32,2083.43 C41.1@1464.6,2105.71 1441.88,2128.43 v1(1394.91,2128.43) ; v2(1740.16,3405.51) U9.14@1740.16,3452.76 ; U9.43@1803.15,3901.57 v2(1803.15,3948.82) C124.1@1803.15,3968.5 ; C128.1@1871.06,3374.01 1889.76,3374.01 1897.64,3381.89 v2(1897.64,3404.53) 1897.64,3405.51 U9.9@1897.64,3452.76 ; U9.49@1992.13,3901.57 v2(1992.13,3948.82) ; R2.1@1995.59,173.23 v1(1995.59,220.47) ; C127.1@2060.05,3377.95 2082.68,3377.95 2086.62,3385.83 2086.62,3389.76 2086.62,3404.53 v2@2086.62,3409.45 ; U9.3@2086.61,3452.76 v2@2086.62,3409.45 ; v2(2087.6,3404.53) v2@2086.62,3409.45 ; C107.1@2141.73,2990.16 C104.1@2185.04,2990.16 2186.02,2989.18 2204.73,2989.18 v1(2212.6,2996.06) ; v2(2149.6,3405.52) 2149.61,3409.45 U9.1@2149.61,3452.76 ; v3(2204.72,4064.96) 2204.72,4037.4 C109.1@2216.53,4025.58 2232.28,4041.34 v3(2232.28,4064.96) ; C103.1@2284.45,3225.39 2284.45,3186.02 2284.45,3182.09 2318.9,3182.09 v1@2330.22,3193.41 ; C102.1@2390.74,2799.21 2389.76,2800.19 2389.76,2842.52 2389.76,2897.64 v1@2409.45,2917.33 ; C139.1@2581.69,3330.7 C143.1@2581.69,3370.07 2582.68,3371.06 2582.68,3393.7 v2(2590.55,3401.57) ; HDR_T1.96@2602.36,2606.3 2602.36,2645.67 ; C140.1@2641.73,4024.61 C140.1@2644.68,4027.56 C144.1@2644.68,3984.24 2644.68,3957.68 v2(2649.61,3952.76) v2@2649.61,3956.7 ; U13.33@2649.88,3901.57 v2@2649.88,3944.88 ; v3(2687.01,3075.79) 2714.58,3075.79 C108.1@2726.39,3087.59 2710.63,3103.35 v3(2687.01,3103.35) ; U1.4@2786.42,2897.63 v2(2786.42,2931.1) C2.1@2786.41,2968.5 C1.2@2786.41,3015.74 ; v2(1330.71,3405.51) U9.27@1330.71,3437.01
  Bottom Layer w19.68: v1(2019.68,2929.13) 2019.68,2886.02 C100.1@2007.68,2874.02 ; v3(2066.93,2842.52) 2016.09,2842.52 C100.1@1996.14,2862.48 C100.1@2007.68,2874.02 ; v3(2066.93,2874.02) C100.1@2007.68,2874.02
  Bottom Layer w27.56: 2570.87,645.67 v3(2570.87,661.42) v3(2570.87,692.91) v3(2570.87,724.41) 2586.62,724.41 ; 2570.87,2645.67 v3(2570.87,2661.42) v3(2570.87,2692.91) v3(2570.87,2724.41) 2586.61,2724.41 ; 2586.62,645.67 2586.62,661.42 2586.62,692.91 2586.62,724.41 ; 2586.61,2645.67 2586.61,2661.42 2586.61,2692.91 2586.61,2724.41 ; 2602.36,645.67 v3(2602.37,661.42) v3(2602.37,692.91) v3(2602.37,724.41) 2586.62,724.41 ; 2602.36,2645.67 v3(2602.36,2661.42) v3(2602.36,2692.91) v3(2602.36,2724.41) 2586.61,2724.41
  other v1: 866.9,1596.05 1169.29,1708.66 655.12,2079.53 2291.34,2917.32 2409.45,2917.32 2330.71,3192.91
  other v2: 1625.98,2693.9 1582.68,3405.51
  other v3: 3011.81,2122.05 2866.14,2149.61 3011.81,2149.61 2866.14,2177.16 3011.81,2177.17
5V0: C113.1 C114.1 C119.1 HDR_B1.97 HDR_B1.99 HDR_T1.97 HDR_T1.99 R19.1 TP4.1 U6.2 U6.4 U7.2 U7.7 | length 4287.4
  Top Layer w12: C119.1@1661.42,2543.31 1684.06,2520.66 U7.2@1736.22,2520.67 U7.7@1917.32,2520.67 1953.34,2520.66 1962.2,2529.53 1962.2,2556.3 1948.5,2570 1859.53,2570 1846.85,2582.68 ; v2(1808.5,2704.6) 1798.1,2715 1765,2715 1760,2710 1760,2669.13 1859.13,2570
  Top Layer w15.75: v3(2460.63,1602.36) 2490.62,1602.36 R19.1@2492.12,1600.86 ; U6.2@2824.58,1658.25 2889.67,1658.25 2889.67,1708.25 U6.4@2824.58,1708.25 ; C113.1@2988.18,1464.56 v3(2988.19,1507.87)
  Top Layer w20: v3(2769.67,1516.41) C114.1@2807.08,1516.41 ; v3(2769.67,1543.97) C114.1@2807.08,1543.97 ; v3(2769.67,1461.29) C114.1@2807.08,1461.29 ; v3(2769.67,1488.85) C114.1@2807.08,1488.85 ; C114.1@2809.04,1461.29 C114.1@2807.08,1461.29 ; C114.1@2809.04,1488.85 C114.1@2807.08,1488.85 ; C114.1@2809.04,1516.41 C114.1@2807.08,1516.41 ; C114.1@2809.04,1543.97 C114.1@2807.08,1543.97 ; 2853.65,1461.29 C114.1@2807.08,1461.29 ; 2857.47,1516.41 C114.1@2807.08,1516.41 ; 2860.42,1543.97 C114.1@2807.08,1543.97 ; 2862.51,1488.85 C114.1@2807.08,1488.85 ; C113.1@2998.04,1461.1 v3(3037.41,1461.1) ; 2998.04,1488.66 v3(3037.41,1488.66) ; v3@2998.04,1516.22 v3(3037.41,1516.22) ; 2998.04,1543.78 v3(3037.41,1543.78)
  Top Layer w43.31: v1@2645.67,2259.84 v1(2645.67,2283.47) 2645.67,2401.58 2736.22,2401.58 2736.22,2346.46 2736.22,2314.96 2736.22,2283.47 2736.22,2259.84 2708.66,2259.84 2677.17,2259.84 v1@2645.67,2259.84
  MidLayer4 w30: 2484.5,2736.3 2508.2,2760 2685,2760 2763.67,2838.67 TP4.1@2875.71,2838.67
  MidLayer4 w43.31: v2@1813.28,2713.28 1832.4,2732.4 2146.5,2732.4 2169.6,2755.5 2465.3,2755.5 2484.5,2736.3 2484.5,2519.44 2657.48,2346.46 v3(2708.66,2346.46)
  Bottom Layer w43.31: 2649.61,263.78 v3@2677.17,263.78 ; v3@2716.54,255.91 2718.5,255.91 2708.66,255.91 2677.17,255.9 2645.67,255.9 v1(2645.67,283.46) 2645.67,338.58 2645.67,354.33 2665.36,354.33 2708.66,354.33 2736.22,354.33 2736.22,346.46 v3@2736.22,314.96 ; v1@2645.67,2259.84 v1(2645.67,2283.47) 2645.67,2338.58 2645.67,2354.33 2665.36,2354.33 2708.66,2354.33 2736.22,2354.33 2736.22,2346.46 2736.22,2314.96 2736.22,2283.47 2736.22,2259.84 2708.66,2259.84 2677.17,2259.84 v1@2645.67,2259.84
  other v1: 2645.67,251.97 2645.67,2251.97
  other v3: 2677.17,251.97 2708.66,251.97 2677.17,283.46 2708.66,283.46 2708.66,314.96 2740.16,314.96 2708.66,346.46 2740.16,346.46 2677.17,2251.97 2708.66,2251.97 2740.16,2251.97 2677.17,2283.47 2708.66,2283.47 2740.16,2283.47 2708.66,2314.96 2740.16,2314.96 2740.16,2346.46
AGND: C111.2 C117.1 NT8.1 R22.2 R23.2 U6.9 U6.11 | length 449.7
  Top Layer w7.87: v3(2397.64,1726.28) 2397.64,1696.85 2401.58,1692.91 C111.2@2425.19,1692.91
  Top Layer w13.78: C117.1@2391.73,1783.46 v3(2452.75,1783.46) ; R23.2@3013.3,1814.96 v3(3047.24,1814.96) ; R22.2@3013.3,1866.14 v3(3047.24,1866.14)
  Top Layer w15.75: U6.9@2589.19,1808.68 2591.08,1808.69 2592.58,1808.69 2661.35,1808.87 2661.35,1808.76 ; U6.11@2591.08,1758.25 U6.11@2592.58,1758.25 2653.67,1758.25 v3(2657.19,1761.76) ; 2657.48,1808.76 2661.35,1808.76 ; v3@2661.35,1758.26 2661.35,1761.76 2661.35,1808.76
  Top Layer w19.68: v3(2397.64,1726.28) 2397.64,1777.55 C117.1@2391.73,1783.46 C117.1@2397.64,1789.37
  other v3: 2519.68,1917.32
BUS_A1: U3.E2 U4.B20 | length 1958.4
  Top Layer w5: U4.B20@1779.53,1925.2 v1(1799.21,1944.88)
  Top Layer w7.87: U3.E2@2350.39,3134.84 v1(2370.08,3153.55)
  MidLayer2 w5: v1(1799.21,1944.88) 1799.21,1956.76 1779.53,1976.45 1779.53,1994.88 1779.53,2018 1897.25,2135.72 1897.25,2178.54 1939.96,2221.26 1985,2221.26 2010,2246.26 2010,2258 2043.31,2291.31 2043.31,2665.35 2051.18,2673.23 2051.18,2688.98 2232.28,2870.08 2232.28,3086.61 2279.53,3133.86 2350.39,3133.86 v1(2370.08,3153.55)
  Bottom Layer w5: v1(2043.31,3149.61) 2098.43,3094.49 2224.41,3094.49 2241.96,3112.04 ; 2242,3112 2263.86,3133.86 2350.39,3133.86 v1(2370.08,3153.55)
BUS_A2: U3.D2 U4.M19 U8.23 U9.23 U12.1 U13.1 | length 5384.2
  Top Layer w5: U4.M19@1740.16,1531.5 v1(1759.84,1551.18) ; U8.23@2023.62,3452.76 v2(2023.62,3503.93) ; U12.1@2271.65,3452.76 v1(2271.65,3500) ; U3.D2@2389.76,3134.84 2390.75,3134.85 v1(2409.45,3153.54)
  MidLayer1 w5: v2(2023.62,3503.93) 2023.62,3523.62 2047.24,3547.24 2224.41,3547.24 v1(2271.65,3500)
  MidLayer2 w5: v1(1759.84,1551.18) 1779.52,1570.86 2010.71,1570.86 2265.17,1825.32 2265.17,2013.26 2496.06,2244.16 2496.06,2263.78 2480.31,2279.53 2480.31,2303.15 2468.5,2314.96 2468.5,2822.83 2547.24,2901.57 2547.24,3086.61 2500,3133.86 2429.13,3133.86 v1(2409.45,3153.54) 2440.94,3185.04 2830.71,3185.04 2850.39,3204.72 2929.72,3204.72 3000,3275 v1(3000,3377.95)
  MidLayer4 w5: v2(1456.69,3381.89) 1456.69,3500 1437.01,3519.68 1437.01,3535.43 1496.06,3594.49 1952.75,3594.49 2023.62,3523.63 v2(2023.62,3503.93) ; v1(2271.65,3500) 2271.65,3519.69 2401.57,3649.61 2937.39,3649.61 3000,3587 v1(3000,3377.95)
  Bottom Layer w5: v2(1456.69,3381.89) U9.23@1456.69,3452.76 ; v1(3000,3377.95) U13.1@3000,3452.76
BUS_A3: U3.C2 U4.M22 U8.24 U9.24 U12.2 U13.2 | length 5328.5
  Top Layer w5: U4.M22@1858.27,1531.5 v1(1877.95,1551.18) ; U8.24@2055.12,3452.76 v2(2055.11,3527.55) ; U12.2@2303.15,3452.76 v1(2303.15,3523.62) ; U3.C2@2429.13,3134.84 2430.12,3134.85 v1(2448.82,3153.54)
  MidLayer1 w5: v2(2055.11,3527.55) 2055.12,3507.87 2094.49,3468.5 2283.46,3468.5 2303.15,3488.19 v1(2303.15,3523.62)
  MidLayer2 w5: v1(1877.95,1551.18) 1897.64,1531.49 2007.49,1531.49 2077.95,1601.95 2077.95,1622.36 2279.93,1824.34 2279.93,2010.31 2507.23,2237.62 2507.23,2250.41 2527.98,2271.16 2527.98,2286.98 2480.31,2334.65 2480.31,2755.91 ; 2480.31,2744.09 2480.31,2818.9 2557.48,2896.06 2557.48,3096.06 2500,3153.54 v1(2448.82,3153.54) 2448.82,3169.29 2452.76,3173.23 2838.58,3173.23 2854.33,3188.98 2931.85,3188.98 2953.81,3210.94 2960.94,3210.94 2997.73,3247.73 2997.73,3254.85 3019.68,3276.81 3019.68,3385.83 3003.94,3401.57 v1(2968.5,3401.57)
  MidLayer4 w5: v2(1425.2,3405.51) 1425.2,3472.44 1405.51,3492.13 1405.51,3511.81 1417.32,3523.62 1417.32,3535.43 1488.19,3606.3 1976.37,3606.3 v2(2055.11,3527.55) ; v1(2303.15,3523.62) 2307.09,3523.62 2421.26,3637.8 2932.21,3637.79 2987,3583 2987,3420.07 v1(2968.5,3401.57)
  Bottom Layer w5: v2(1425.2,3405.51) U9.24@1425.2,3452.76 ; v1(2968.5,3401.57) U13.2@2968.5,3452.76
BUS_A4: U3.A2 U4.P26 U8.25 U9.25 U12.3 U13.3 | length 4894.5
  Top Layer w5: U4.P26@2015.75,1452.76 2032.65,1452.76 2071.62,1491.73 2176.11,1491.73 2322.83,1638.46 2322.83,2050.27 2509.2,2236.63 2509.2,2253.29 2527.56,2271.65 2527.56,2302.56 2502.31,2327.81 2502.31,2762.15 2557.76,2817.6 2639.37,2899.21 2639.37,3075.2 2562.01,3152.55 2525.58,3152.55 U3.A2@2507.87,3134.84 ; U8.25@2086.61,3452.76 v2(2086.61,3503.93) ; U12.3@2334.64,3452.76 v1(2334.64,3500)
  MidLayer1 w5: v1(2550.19,3152.55) 2699.8,3152.55 2879.76,3332.52 2899.45,3332.52 v1(2937.01,3370.08)
  MidLayer4 w5: v2(1393.7,3527.56) 1484.25,3618.11 1992.62,3618.11 2086.61,3524.12 v2(2086.61,3503.93) 2110.23,3480.32 2314.96,3480.32 v1(2334.64,3500) 2334.64,3535.43 2425.19,3625.98 2923.02,3625.98 2976,3573 2976,3441 2937.01,3402.01 v1(2937.01,3370.08)
  Bottom Layer w5: U9.25@1393.7,3452.76 v2(1393.7,3527.56) ; U13.3@2933.07,3452.76 U13.3@2933.07,3430.12 ; v1(2937.01,3370.08) 2937.01,3413.39 2933.07,3417.32 U13.3@2933.07,3430.12 ; U13.3@2937.01,3434.05 U13.3@2933.07,3430.12
BUS_A5: U3.B2 U4.N20 U8.26 U9.26 U12.4 U13.4 | length 5297.6
  Top Layer w5: U4.N20@1779.53,1492.13 1800.06,1471.59 2029.49,1471.59 2059.84,1501.94 2167.01,1501.94 2311.02,1645.95 2311.02,2062.93 2496.06,2247.97 2496.06,2263.78 2488.19,2271.65 2488.19,2763.78 2626.77,2902.36 2626.77,3059.05 2571.65,3114.17 v1(2488.19,3114.17) 2468.51,3133.86 U3.B2@2468.5,3134.84 ; U8.26@2118.11,3452.76 v2(2118.11,3527.55) ; U12.4@2366.14,3452.76 v1(2366.14,3523.62)
  MidLayer1 w5: v2(2118.11,3527.55) 2165.34,3480.32 2279.53,3480.32 2291.34,3492.13 2291.34,3507.87 2281.65,3517.56 2281.65,3529.68 2299.21,3547.24 2342.52,3547.24 v1(2366.14,3523.62) ; v1(2488.19,3114.17) 2488.19,3133.86 2527.56,3173.23 2703.74,3173.23 2873.03,3342.52 2888.27,3342.52 2913.39,3367.64 v1(2913.39,3401.57)
  MidLayer4 w5: v2(1362.2,3405.51) 1362.2,3472.44 1342.52,3492.13 1342.52,3511.81 1460.63,3629.92 2015.74,3629.92 v2(2118.11,3527.55) ; v1(2366.14,3523.62) 2366.14,3535.43 2433.07,3602.36 2893.7,3602.36 2924.7,3571.36 2924.7,3524.11 2933.07,3515.75 2933.07,3421.26 v1(2913.39,3401.57)
  Bottom Layer w5: v2(1362.2,3405.51) U9.26@1362.21,3452.76 ; U13.4@2905.51,3448.82 U13.4@2901.57,3452.76 2901.57,3413.39 v1(2913.39,3401.57)
BUS_A6: U3.D3 U4.D21 U8.29 U9.29 U12.5 U13.5 | length 4680.2
  Top Layer w5: U4.D21@1818.9,1846.46 v1(1838.58,1866.14) ; v2(2118.1,3850.39) U8.29@2118.11,3901.57 ; U12.5@2397.64,3452.76 v1(2397.64,3500)
  Top Layer w7.87: U3.D3@2389.77,3095.48 v1(2409.45,3114.18)
  MidLayer1 w5: v1(2409.45,3114.18) 2425.2,3114.18 2429.13,3118.11 2429.13,3122.05 2440.94,3133.86 2472.44,3133.86 2523.62,3185.04 2700.79,3185.04 v1(2881.89,3366.14)
  MidLayer2 w5: v1(1838.58,1866.14) 1858.27,1885.83 1858.27,1916.93 1866.54,1925.2 1885.83,1925.2 1897.64,1937.01 1897.64,2030.64 1954,2087 2030.06,2087 2103.79,2160.74 2103.79,2230.19 2118.11,2244.5 2118.11,2263.78 2106.3,2275.59 2106.3,2291.34 2122.05,2307.09 2122.05,2645.67 2110.24,2657.48 2110.24,2673.23 2311.02,2874.02 2311.02,3082.68 2322.83,3094.49 2350.39,3094.49 2370.08,3114.18 v1(2409.45,3114.18)
  MidLayer3 w5: v2(2118.1,3850.39) 2118.11,3822.84 2397.64,3543.31 v1(2397.64,3500)
  MidLayer4 w5: v2(1362.2,3948.82) 1362.2,3885.83 1342.52,3866.14 1342.52,3842.52 1460.63,3724.41 2011.81,3724.41 2118.1,3830.7 v2(2118.1,3850.39) ; v1(2397.64,3500) 2397.64,3535.93 2440.45,3578.74 2854.33,3578.74 2866.14,3566.93 2866.14,3555.86 2889.76,3532.24 2889.76,3515.75 2881.89,3507.87 v1(2881.89,3366.14)
  Bottom Layer w5: U9.29@1362.2,3901.59 v2(1362.2,3948.82) ; U13.5@2870.08,3452.76 2870.08,3433.07 2881.89,3421.26 v1(2881.89,3366.14)
BUS_A7: U3.C3 U4.L17 U8.30 U9.30 U12.18 U13.18 | length 5065.4
  Top Layer w5: U4.L17@1661.42,1570.87 v1(1681.1,1590.55) ; v2(2086.61,3826.77) U8.30@2086.61,3901.57 ; U12.18@2807.09,3452.76 2807.09,3496.06 2826.77,3515.75 2826.77,3527.56 v1(2846.46,3555.12)
  Top Layer w7.87: U3.C3@2429.14,3095.48 v1(2448.82,3114.17)
  MidLayer2 w5: v1(1681.1,1590.55) 1700.79,1610.24 1932.68,1610.24 1935.43,1607.48 1972.44,1607.48 1975.2,1610.24 2026.47,1610.24 2250.49,1834.26 2250.49,2015.32 2456.69,2221.52 2456.69,2263.78 2468.5,2275.59 2468.5,2295.28 2456.69,2307.09 2456.69,2826.77 2507.87,2877.95 2507.87,3082.68 2496.06,3094.49 2468.5,3094.49 v1(2448.82,3114.17) ; v1(2688.98,3295.28) 2795.28,3401.57 2795.28,3484.25 2826.77,3515.75 2826.77,3535.43 v1(2846.46,3555.12)
  MidLayer3 w5: v2(2086.61,3826.77) 2086.61,3858.26 2098.43,3870.08 2125.98,3870.08 2137.8,3858.27 2137.8,3826.77 2409.45,3555.12 2409.45,3515.75 2460.63,3464.57 v2(2460.63,3401.57)
  MidLayer4 w5: v2(1393.7,3826.77) 1484.25,3736.22 1996.06,3736.22 v2(2086.61,3826.77) ; v2(2460.63,3401.57) 2519.68,3460.63 2771.65,3460.63 2826.77,3515.75 2826.77,3535.43 v1(2846.46,3555.12)
  Bottom Layer w5: v2(1393.7,3826.77) U9.30@1393.7,3901.57 ; v1(2448.82,3114.17) 2559.06,3224.41 2606.3,3224.41 2610.24,3228.35 2629.92,3248.03 2629.92,3263.78 2641.73,3275.59 2657.48,3275.59 2669.29,3287.4 2669.29,3291.34 2673.23,3295.28 v1(2688.98,3295.28) ; v2(2460.63,3401.57) U13.18@2460.63,3452.76 U13.18@2460.63,3472.44
BUS_A8: U3.A3 U4.M25 U8.31 U9.31 U12.19 U13.19 | length 4959.5
  Top Layer w5: U4.M25@1976.38,1531.5 1995.7,1512.17 2159.12,1512.17 2299.21,1652.26 2299.21,2082.73 2456.69,2240.21 2456.69,2263.78 2464.57,2271.65 2464.57,2755.91 2613.78,2905.12 2613.78,3039.76 2578.74,3074.8 v1(2527.56,3074.8) ; v2(2055.11,3850.39) U8.31@2055.12,3901.57 ; U12.19@2838.58,3452.76 2838.58,3472.44 2858.27,3492.13 2858.27,3511.81 v1(2870.08,3523.62)
  Top Layer w7.87: U3.A3@2507.88,3095.48 v1(2527.56,3074.8)
  MidLayer2 w5: v1(2688.98,3240.16) 2708.66,3240.16 2826.77,3358.27 2826.77,3366.14 2826.77,3437.01 2870.08,3480.31 v1(2870.08,3523.62)
  MidLayer3 w5: v2(2055.11,3850.39) 2055.11,3818.9 2080.55,3793.46 2123.86,3793.46 2370.08,3547.24 2385.83,3531.5 2385.83,3515.28 2385.36,3515.28 2377.95,3507.87 2377.95,3480.32 2429.13,3429.13 v1(2429.13,3377.95)
  MidLayer4 w5: v2(1425.2,3948.82) 1425.2,3885.83 1421.26,3881.89 1405.51,3866.14 1405.51,3842.52 1417.32,3830.71 1417.32,3822.83 1492.13,3748.03 1976.38,3748.03 2055.11,3826.77 v2(2055.11,3850.39) ; v1(2429.13,3377.95) 2448.82,3358.27 2511.81,3358.27 2594.49,3440.94 2811.02,3440.94 2858.27,3488.19 2858.27,3511.81 v1(2870.08,3523.62)
  Bottom Layer w5: U9.31@1425.2,3901.57 v2(1425.2,3948.82) ; v1(2429.13,3377.95) U13.19@2429.13,3452.76 ; v1(2527.56,3074.8) 2527.56,3094.49 2673.23,3240.16 v1(2688.98,3240.16)
BUS_A9: U3.B6 U4.M26 U8.32 U9.32 U12.20 U13.20 | length 5007.8
  Top Layer w5: U4.M26@2017.72,1531.5 U4.M26@2015.75,1531.5 2036.22,1531.5 v1(2097.64,1592.91) ; v2(2023.62,3826.77) U8.32@2023.62,3901.57 ; U12.20@2870.08,3452.76 2870.08,3496.06 2901.57,3527.56 v1(2901.57,3562.99)
  Top Layer w7.87: U3.B6@2468.5,2977.36 v1@2488.19,2957.68
  MidLayer1 w5: v1(2097.64,1592.91) 2097.64,1646.97 2309.63,1858.96 2309.63,2076.42 2454.1,2220.89 2454.1,2261.18 2468.5,2275.59 2468.5,2323.85 2487.55,2342.9 2487.55,2869.42 2507.88,2889.75 ; v1@2488.68,2957.19 2507.87,2938 ; 2507.88,2890.01 2507.87,2937.01
  MidLayer3 w5: v2(2023.62,3826.77) 2066.93,3783.46 2102.36,3783.46 2122.05,3763.78 2346.46,3539.37 2346.46,3515.75 2366.14,3496.06 2366.14,3433.07 v2(2397.64,3401.57) ; v1(2822.83,3220.47) 2822.7,3238.32 2814.96,3246.06 2814.96,3277.56 2831.69,3294.29 2831.69,3343.5 2881.89,3393.7 2881.89,3507.87 2901.57,3527.56 ; 2901.57,3527.56 v1(2901.57,3562.99)
  MidLayer4 w5: v2(1456.69,3948.82) 1456.69,3854.33 1437.01,3834.65 1437.01,3818.9 1496.06,3759.84 1956.69,3759.84 v2(2023.62,3826.77) ; v2(2397.64,3401.57) 2397.64,3358.27 2429.13,3326.77 2877.95,3326.77 2905.51,3354.33 2905.51,3377.95 2893.7,3389.76 2893.7,3464.57 2921.26,3492.13 2921.26,3507.87 2913.39,3515.75 2913.39,3551.18 v1(2901.57,3562.99)
  Bottom Layer w5: U9.32@1456.69,3901.57 v2(1456.69,3948.82) ; v2(2397.64,3401.57) U13.20@2397.64,3452.76 ; v1(2488.19,2956.69) 2488.19,2992.98 2715.68,3220.47 v1(2822.83,3220.47)
BUS_A10: U3.A6 U4.M18 U8.33 U9.33 U12.21 U13.21 | length 5321.7
  Top Layer w5: U4.M18@1700.79,1531.5 v1(1720.47,1551.18) ; v2(1992.12,3850.39) U8.33@1992.13,3901.57 ; U3.A6@2507.87,2977.36 2507.87,2977.16 2563.39,2977.16 v1(2584.25,2956.3) ; U12.21@2901.57,3452.76 v1(2901.57,3500)
  MidLayer2 w5: v1(2537.8,2142.91) 2537.8,2157.09 2559.05,2178.35 2559.05,2271.65 2490.5,2340.2 2490.5,2807.43 2584.25,2901.18 v1(2584.25,2956.3) ; v1(2835.63,3259.84) 2835.63,3284.45 2901.57,3350.39 2901.57,3381.89 2893.7,3389.76 2893.7,3468.5 2901.57,3476.38 v1(2901.57,3500)
  MidLayer3 w5: v2(1992.12,3850.39) 1992.12,3811.03 2031.5,3771.65 2098.43,3771.65 2322.83,3547.24 2322.83,3515.75 2314.96,3507.87 2314.96,3448.82 2366.14,3397.64 v1(2366.14,3377.95)
  MidLayer4 w5: v2(1488.19,3850.39) 1488.19,3814.96 1531.5,3771.65 1937.01,3771.65 1992.12,3826.77 v2(1992.12,3850.39) ; v1@1721,1551.18 1740.69,1570.88 1925.18,1570.88 1974.7,1521.36 2012.7,1521.36 2054.53,1563.19 2188.39,1563.19 2320.97,1695.78 2398.67,1695.78 2425.86,1722.96 2425.86,2020.35 2537.8,2132.29 v1(2537.8,2142.91) ; v1(2366.14,3377.95) 2366.14,3496.06 2385.36,3515.28 2385.83,3515.28 2385.83,3540.11 2436.27,3590.55 2862.2,3590.55 2877.95,3574.8 2877.95,3559.06 2901.57,3535.43 v1(2901.57,3500)
  Bottom Layer w5: v2(1488.19,3850.39) U9.33@1488.19,3901.57 ; v1(2366.14,3377.95) U13.21@2366.14,3452.76 ; v1(2584.25,2956.3) 2606.3,2978.35 2606.3,3096.85 2710.23,3200.79 2831.69,3200.79 2842.52,3211.61 2842.52,3232.29 2835.63,3239.17 v1(2835.63,3259.84) v1@2836.54,3258.79
BUS_A11: U3.C6 U4.M21 U8.34 U9.34 U12.22 U13.22 | length 5112.7
  Top Layer w5: U4.M21@1818.9,1531.5 v1(1838.58,1551.18) ; v2(1960.62,3826.77) U8.34@1960.63,3901.57 ; U12.22@2933.07,3452.76 2933.07,3519.68 v1(2944.88,3531.5)
  Top Layer w7.87: U3.C6@2429.13,2977.36 v1@2448.82,2957.68
  MidLayer1 w5: v1(1838.58,1551.18) 1858.27,1570.87 1997.26,1570.87 ; 1997.64,1570.87 2003.94,1570.87 2012.22,1579.15 2299.5,1866.43 2299.5,2086.95 2433.07,2220.53 2433.07,2263.78 2421.26,2275.59 2421.26,2299.21 2468.51,2346.46 2468.51,2937.99 v1@2448.82,2957.68
  MidLayer2 w5: v1(2944.88,3531.5) 2944.88,3393.7 2956.69,3381.89 2956.69,3358.27 2952.76,3354.33 2937.01,3338.58 2937.01,3297.24 v1(2964.57,3269.68)
  MidLayer3 w5: v2(1960.62,3826.77) 2027.56,3759.84 2094.49,3759.84 2279.53,3574.8 2279.53,3519.68 2291.34,3507.87 2291.34,3444.88 v2(2334.65,3401.57)
  MidLayer4 w5: v2(1519.68,3948.82) 1519.68,3854.33 1500,3834.65 1500,3818.9 1535.43,3783.46 1917.32,3783.46 v2(1960.62,3826.77) ; v2(2334.65,3401.57) 2334.65,3472.44 2354.33,3492.13 2354.33,3507.87 2346.46,3515.75 2346.46,3531.5 2429.13,3614.17 2897.64,3614.17 2944.88,3566.93 v1(2944.88,3531.5) ; v1(2448.82,2956.69) 2468.5,2976.38 2649.61,2976.38 2858.27,3185.04 2909.45,3185.04 2964.57,3240.16 2964.57,3266.73 v1@2961.61,3269.68
  Bottom Layer w5: U9.34@1519.69,3901.57 v2(1519.68,3948.82) ; v2(2334.65,3401.57) U13.22@2334.65,3452.76
BUS_A12: U3.D6 U4.K25 U8.22 U9.22 U12.23 U13.23 | length 5361
  Top Layer w5: U4.K25@1976.38,1610.24 v1(1996.06,1629.92) ; U8.22@1992.13,3452.76 v2(1992.12,3527.55) ; v2(2933.07,3850.39) U12.23@2933.07,3901.57
  Top Layer w7.87: U3.D6@2389.76,2977.36 v1@2409.45,2957.68
  MidLayer1 w5: v1@1996.46,1630.32 v1(1996.06,1629.92) 2043.2,1629.92 2289.21,1875.93 2289.21,2095.37 2393.7,2199.85 2393.7,2263.78 2405.51,2275.59 2405.51,2303.15 2417.32,2314.96 2417.32,2665.35 2433.07,2681.1 2433.07,2696.85 2393.7,2736.22 2393.7,2874.02 2429.14,2909.46 2429.14,2937 v1(2409.45,2956.69) 2409.45,2957.68 v1@2409.94,2957.19
  MidLayer2 w5: v2(1992.12,3527.55) 2023.62,3559.06 2141.73,3559.06 2314.96,3732.28 2314.96,3834.64 2326.77,3846.46 v2(2326.77,3952.76) ; v2(2933.07,3850.39) 2933.07,3610.24 3043.31,3500 3043.31,3240.16 v1(2988.19,3185.04)
  MidLayer4 w5: v2(1488.19,3503.94) 1488.19,3539.37 1531.5,3582.68 1937,3582.68 v2(1992.12,3527.55) ; v2(2326.77,3952.76) 2326.77,3933.07 2334.65,3925.2 2334.65,3854.33 2354.33,3834.65 2354.33,3811.02 2370.08,3795.28 2913.39,3795.28 2933.07,3814.96 v2(2933.07,3850.39) ; v1(2409.45,2956.69) 2429.13,2937.01 2547.24,2937.01 2563.39,2920.87 2714.96,2920.87 2800,3005.91 2800,3060 2830,3090 2950,3090 2988.19,3128.19 v1(2988.19,3185.04)
  Bottom Layer w5: U9.22@1488.19,3452.76 v2(1488.19,3503.94) ; v2(2326.77,3952.76) 2326.77,3929.13 2334.65,3921.26 U13.23@2334.65,3901.57
BUS_A13: U3.B7 U4.L18 U8.35 U9.35 U12.24 U13.24 | length 5426.1
  Top Layer w5: U4.L18@1700.79,1570.87 v1(1720.47,1590.55) ; v2(1929.13,3850.39) U8.35@1929.13,3901.57 ; v1(2104.72,1903.54) 2125.98,1882.28 2239.48,1882.28 2272.06,1914.86 2272.06,2182.06 2311.81,2221.81 2311.81,2259.06 2299.31,2271.56 2299.31,2293.7 2433.07,2427.46 2433.07,2756.79 ; 2433.07,2740.16 2433.07,2807.09 2488.19,2862.21 v1(2488.19,2917.32) 2488.19,2918.31 U3.B7@2468.5,2937.99 ; v2(2901.57,3826.77) U12.24@2901.57,3901.57
  MidLayer1 w5: v2(1929.13,3850.39) 1929.13,3913.39 2011.81,3996.06 2322.83,3996.06 v2(2366.14,3952.76)
  MidLayer2 w5: v2(2901.57,3826.77) 2913.39,3814.96 2913.39,3606.3 3031.5,3488.19 3031.5,3259.84 v1(2956.69,3185.04)
  MidLayer4 w5: v2(1551.18,3948.82) 1551.18,3881.89 1531.5,3862.2 1531.5,3842.52 1578.74,3795.28 1897.64,3795.28 1929.13,3826.77 v2(1929.13,3850.39) ; v1(1720.47,1590.55) 1720.47,1591.1 1700.5,1611.07 1700.5,1637.51 1751.67,1688.68 1846.06,1688.68 1857.89,1700.51 1857.89,1716.95 1859.81,1718.87 ; 1859.71,1718.77 1869.67,1728.72 1927.95,1728.72 1936.63,1737.4 1936.63,1796.87 1947.23,1807.46 1966.54,1807.46 1976,1816.93 1976,1839.22 1983.46,1846.68 2047.86,1846.68 v1(2104.72,1903.54) ; v2(2366.14,3952.76) 2421.26,4007.87 2834.65,4007.87 2858.27,3984.25 2858.27,3968.5 2850.39,3960.63 2850.39,3905.51 2889.76,3866.14 2889.76,3838.58 v2(2901.57,3826.77)
  Bottom Layer w5: U9.35@1551.18,3881.89 U9.35@1551.18,3901.57 v2(1551.18,3948.82) ; U13.24@2366.14,3901.57 v2(2366.14,3952.76) ; v1(2488.19,2917.32) 2507.87,2897.64 2579.13,2897.64 2730.5,3049 2829,3049 2870,3090 2930,3090 2956.69,3116.69 v1(2956.69,3185.04)
BUS_A14: U3.A7 U4.K26 U8.36 U9.36 U12.25 U13.25 | length 4890.6
  Top Layer w5: v2(1897.63,3826.77) U8.36@1897.64,3901.57 ; U4.K26@2015.75,1610.24 2028.74,1623.23 2228.35,1623.23 2288.98,1683.86 2288.98,2090.21 2440.55,2241.78 2440.55,2256.3 2425.2,2271.65 2425.2,2292.12 2453.54,2320.47 2453.54,2762.99 2527.56,2837.01 v1(2527.56,2917.32) ; v2(2870.08,3850.39) U12.25@2870.08,3901.57
  Top Layer w7.87: U3.A7@2507.87,2937.99 v1@2527.56,2918.31
  MidLayer1 w5: v2(1897.63,3826.77) 1897.64,3921.26 1917.32,3940.94 1917.32,3956.69 1909.45,3964.57 1909.45,3980.32 1921.26,3992.13 1988.19,3992.13 2003.94,4007.87 2342.52,4007.87 v2(2397.64,3952.76)
  MidLayer3 w5: v2(2870.08,3850.39) 2881.89,3838.58 2881.89,3814.96 2921.26,3775.59 2921.26,3555.12 2913.39,3547.24 2913.39,3515.75 2921.26,3507.87 2921.26,3444.88 2893.7,3417.32 2893.7,3389.76 2901.57,3381.89 2901.57,3354.33 2897,3349.76 2897,3300.06 2934.06,3263 v1(2934.06,3166.34)
  MidLayer4 w5: v2(1582.68,3830.71) 1606.3,3807.09 1877.95,3807.09 v2(1897.63,3826.77) ; v2(2397.64,3952.76) 2440.94,3996.06 2791.34,3996.06 2838.58,3948.82 2838.58,3881.89 v2(2870.08,3850.39)
  Bottom Layer w5: v2(1582.68,3830.71) U9.36@1582.68,3901.57 ; U13.25@2397.64,3901.57 v2(2397.64,3952.76) ; v1(2527.56,2917.32) 2583.86,2917.32 2616.5,2949.97 2616.5,3092.88 2712.6,3188.98 2911.42,3188.98 v1(2934.06,3166.34)
BUS_A15: U3.C7 U4.J21 U8.20 U9.20 U12.26 U13.26 | length 4938.6
  Top Layer w5: U4.J21@1818.9,1649.61 v1(1838.58,1669.29) ; U8.20@1929.13,3452.76 v2(1929.13,3527.55) ; v1(2230.73,1907.98) 2210.06,1928.64 2210.06,1952.26 2239.58,1981.78 2239.58,2233.58 2241,2235 ; 2241.15,2234.85 2250,2243.7 2250,2257.87 2236.42,2271.46 2236.42,2290.94 2358.27,2412.8 2358.27,2669.29 2370.08,2681.1 2370.08,2795.28 2448.82,2874.02 v1(2448.82,2917.32) ; U3.C7@2429.13,2937.99 v1@2448.82,2918.31 ; v2(2838.58,3826.77) U12.26@2838.58,3901.57
  MidLayer2 w5: v2(1929.13,3527.55) 1972.44,3570.87 2129.92,3570.87 2291.34,3732.28 2291.34,3834.65 2283.46,3842.52 2283.46,3859.06 2307.09,3882.68 2307.09,3960.63 2318.9,3972.44 2409.45,3972.44 v2(2429.13,3952.76) ; v1(2681.1,3267.72) 2696.85,3267.72 2811.02,3381.89 2811.02,3440.94 2858.27,3488.19 2858.27,3507.87 2850.39,3515.75 2850.39,3531.5 2866.14,3547.25 2866.14,3574.8 2846.46,3594.49 2846.46,3673.23 2834.64,3685.04 2834.64,3704.72 2838.58,3708.66 v2(2838.58,3826.77)
  MidLayer3 w5: v1(2448.82,2917.32) 2468.5,2937.01 2516.14,2937.01 2527.95,2948.82 2527.95,3032.68 2653.97,3158.69 ; 2654.12,3158.85 2668.91,3173.64 2668.91,3255.53 v1(2681.1,3267.72)
  MidLayer4 w5: v2(1551.18,3405.51) 1551.18,3476.38 1531.5,3496.06 1531.5,3511.81 1543.31,3523.62 1543.31,3535.43 1566.93,3559.06 1897.63,3559.06 v2(1929.13,3527.55) ; v1(1838.58,1669.29) 1850.39,1669.29 1869.7,1688.6 1947.13,1688.6 1986.61,1728.08 2091.47,1728.08 2206.27,1842.89 ; 2206.13,1843.03 2230.73,1867.63 v1(2230.73,1907.98) v1@2230.73,1908.96 ; v2(2429.13,3952.76) 2429.13,3929.13 2472.44,3885.83 2744.09,3885.83 2803.15,3826.77 v2(2838.58,3826.77)
  Bottom Layer w5: v2(1551.18,3405.51) U9.20@1551.18,3452.76 ; U13.26@2429.13,3901.57 v2(2429.13,3952.76)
